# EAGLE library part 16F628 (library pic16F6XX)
Microchip component PIC 16F628 Eric Magraner - eric_magraner@yahoo.fr 03/2004
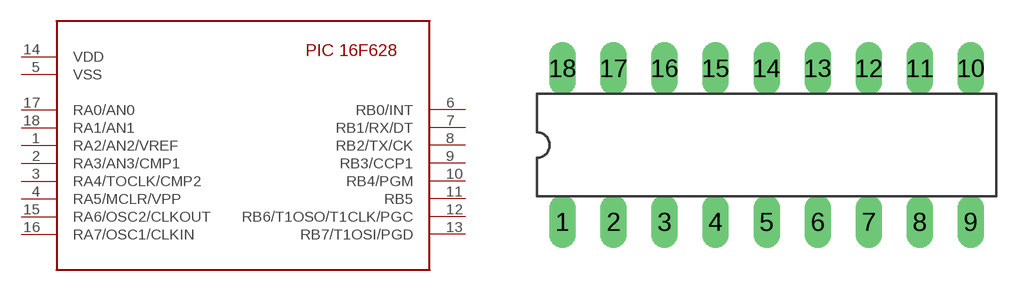
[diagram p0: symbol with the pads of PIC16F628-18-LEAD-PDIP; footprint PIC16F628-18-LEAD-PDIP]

Designator prefix -

## 16F628  [PIC16F628-18-LEAD-PDIP]
1  RA2/AN2/VREF
2  RA3/AN3/CMP1
3  RA4/TOCLK/CMP2
4  RA5/MCLR/VPP
5  VSS  in
6  RB0/INT
7  RB1/RX/DT
8  RB2/TX/CK
9  RB3/CCP1
10  RB4/PGM
11  RB5
12  RB6/T1OSO/T1CLK/PGC
13  RB7/T1OSI/PGD
14  VDD  in
15  RA6/OSC2/CLKOUT
16  RA7/OSC1/CLKIN
17  RA0/AN0
18  RA1/AN1

## Footprint PIC16F628-18-LEAD-PDIP (pad centres in mm)
Dual In Line package type P Microchip component PIC 16F628 Eric Magraner - eric_magraner@yahoo.fr 03/2004
drill 0.813 long: 1 -10.16,-3.81; 2 -7.62,-3.81; 3 -5.08,-3.81; 4 -2.54,-3.81; 5 0,-3.81; 6 2.54,-3.81; 7 5.08,-3.81; 8 7.62,-3.81; 9 10.16,-3.81; 10 10.16,3.81; 11 7.62,3.81; 12 5.08,3.81; 13 2.54,3.81; 14 0,3.81; 15 -2.54,3.81; 16 -5.08,3.81; 17 -7.62,3.81; 18 -10.16,3.81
